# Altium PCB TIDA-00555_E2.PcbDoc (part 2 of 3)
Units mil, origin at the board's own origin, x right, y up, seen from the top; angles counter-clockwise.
Board outline 6490 x 3985 mil, 4 copper layers (Top Layer, MidLayer1, MidLayer2, Bottom Layer), stack 61.2 mil thick; 376 components, 194 nets, 936 pads, 294 vias.
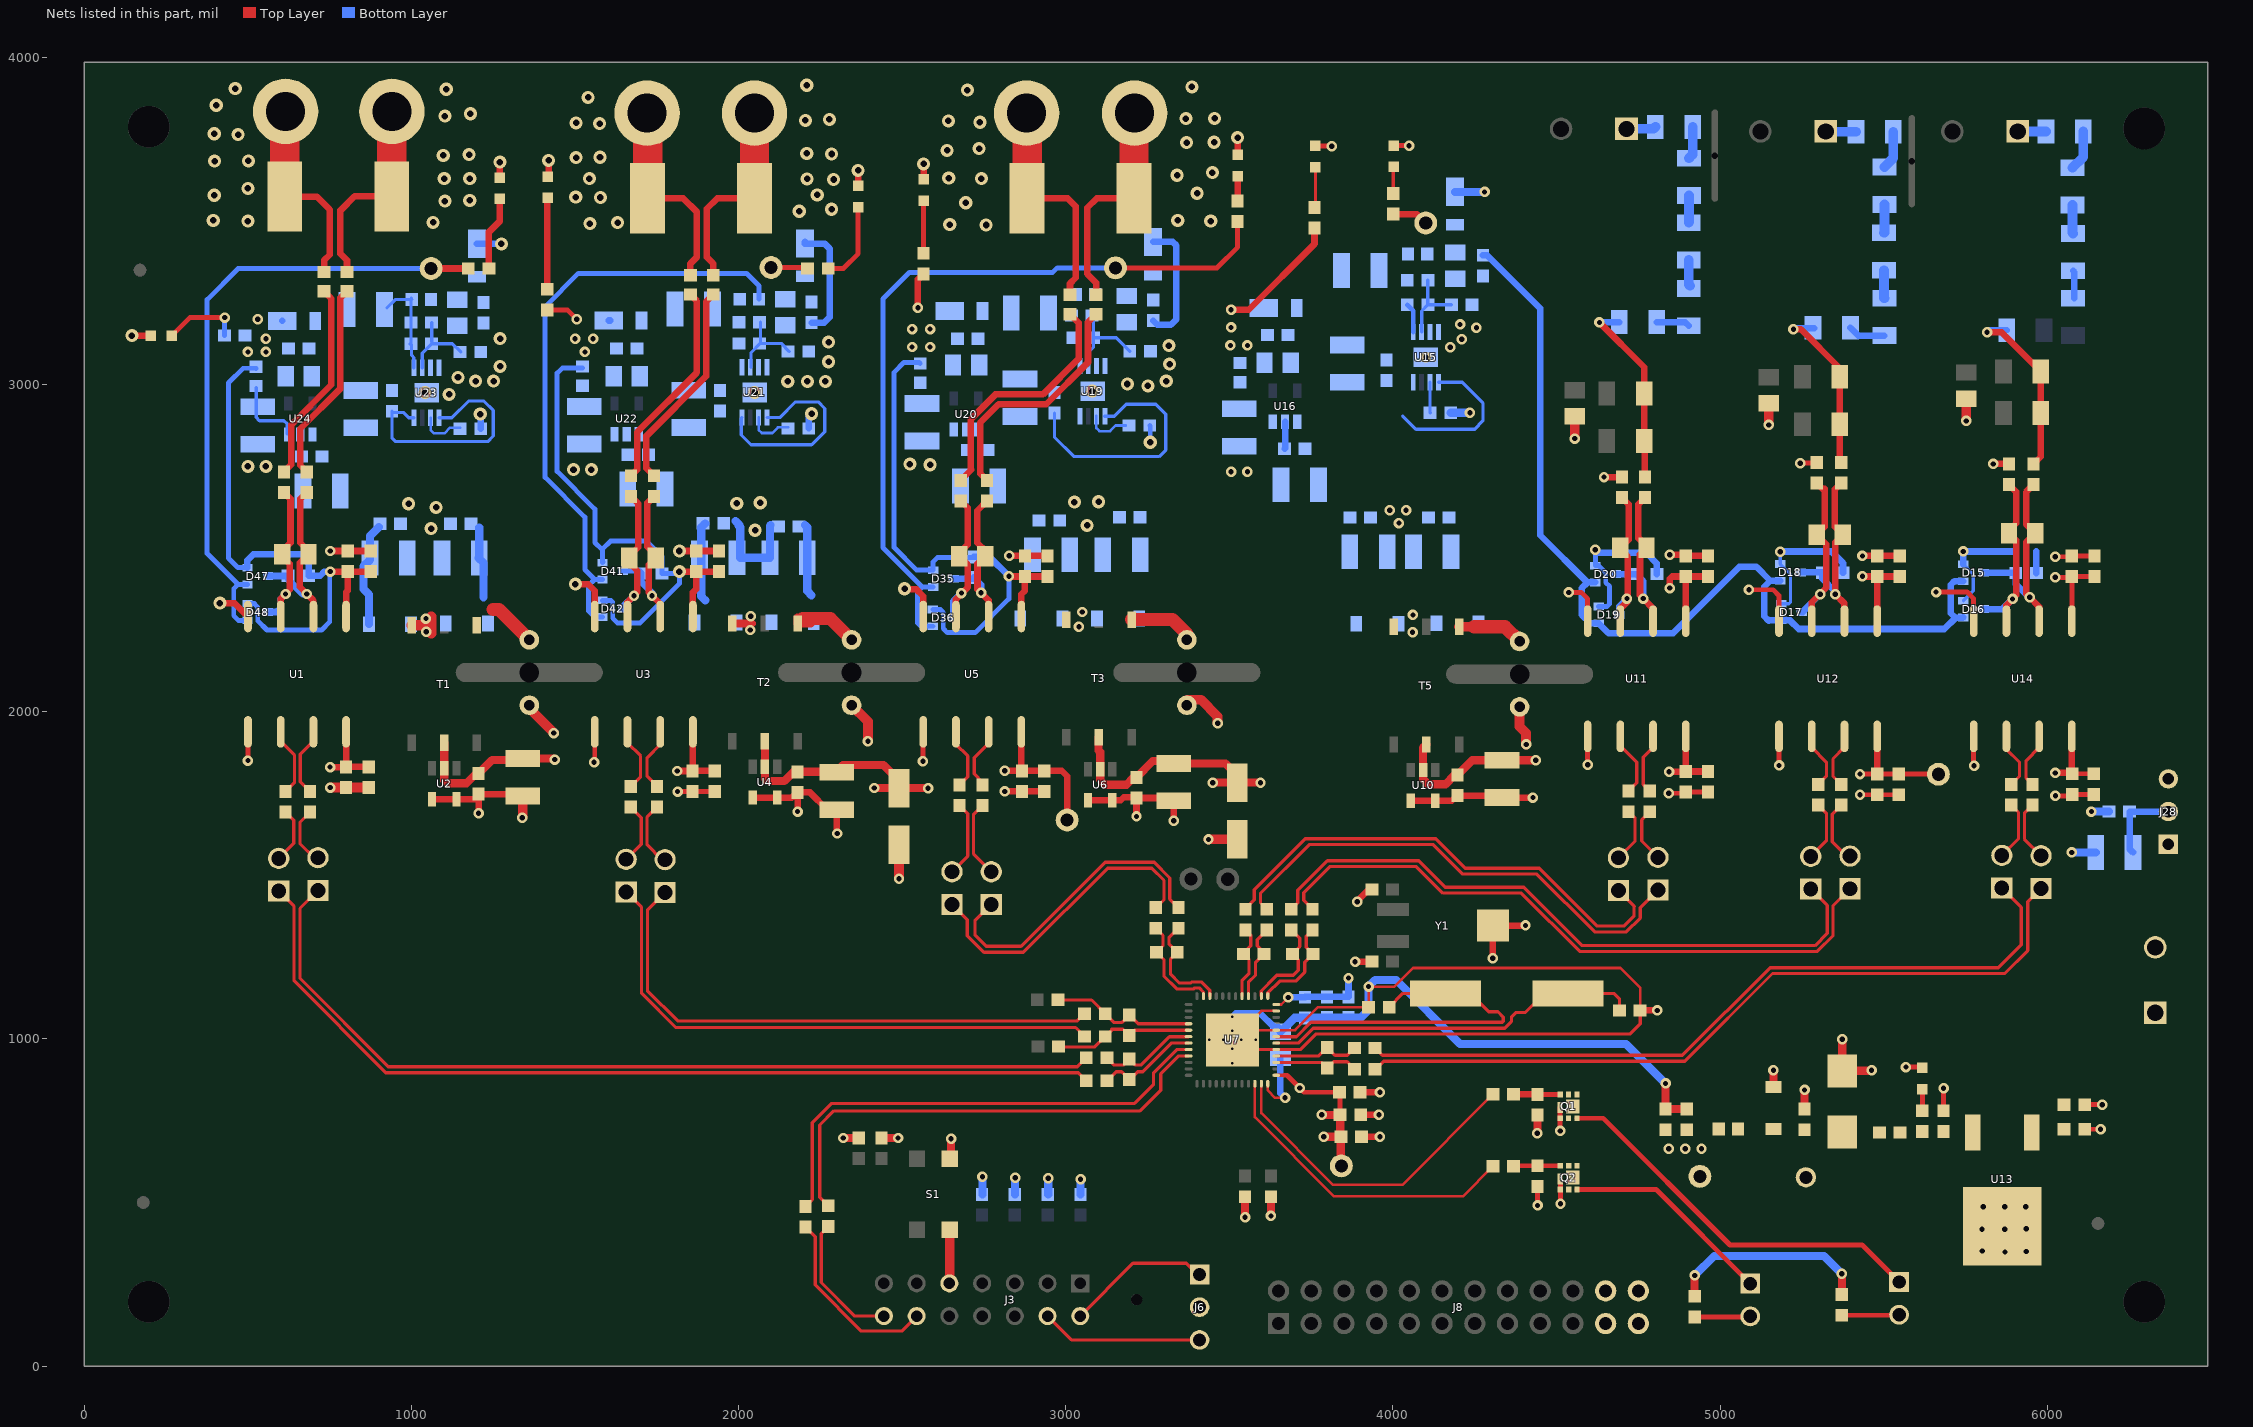
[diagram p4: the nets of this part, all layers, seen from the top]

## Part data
C1 C3 C4 C8 C11 C12 C17 C19 C20 C57 C64 C70: library part 06033C104JAT2A, "CAP, CERM, 0.1uF, 25V, +/-5%, X7R, 0603"
C2 C9 C18 C55 C61 C68: "CAP, CERM, 330 pF, 50 V, +/- 10%, C0G/NP0, 0805"
C5 C13 C23 C30 C49 C71 C75 C78 C80 C83 C85 C106 C109 C113 C114 C118 C120 C122 C125 C129 C130 C134 C136 C138 C141 C145 C146 C150 C152: library part C0603C104K5RACTU, "CAP, CERM, 0.1uF, 50V, +/-10%, X7R, 0603"
C6 C14 C25 C27 C50 C73 C77 C79 C81 C82 C86 C108 C112 C115 C116 C117 C121 C123 C128 C131 C132 C133 C137 C139 C144 C147 C148 C149 C153: library part GMK325AB7106MM-T, "CAP, CERM, 10uF, 35V, +/-20%, X7R, 1210"
C7 C15 C26 C51: library part 202R18W102KV4E, "CAP CER 1000PF 1KV 10% RADIAL"
C10: "CAP, CERM, 1000 pF, 50 V, +/- 10%, C0G/NP0, 0603"
C16 C28: "CAP, AL, 22uF, 25V, +/-20%, 0.76 ohm, SMD"
C21 C22 C24 C29 C32 C34: "CAP, CERM, 100 pF, 50 V, +/- 5%, C0G/NP0, 0603"
C31 C33 C35 C38 C42 C43 C44 C45 C54 C56 C60 C62 C63 C65 C67 C103: "CAP, CERM, 1 µF, 16 V, +/- 10%, X7R, 0603"
C36 C105: "CAP, CERM, 0.1 µF, 16 V, +/- 5%, X7R, 0603"
C37 C102: "CAP, CERM, 10uF, 25V, +/-20%, X5R, 0603"
C39 C48: "CAP, CERM, 18pF, 50V, +/-5%, C0G/NP0, 0603"
C40 C41: "CAP, CERM, 12pF, 50V, +/-5%, C0G/NP0, 0603"
C46 C47 C52: "CAP, CERM, 0.1uF, 25V, +/-5%, X7R, 0603"
C53: "CAP, CERM, 4.7uF, 10V, +/-10%, X5R, 0603"
C58 C66: "CAP, CERM, 0.1uF, 50V, +/-10%, X7R, 0603"
C59: "CAP, TA, 4.7uF, 35V, +/-10%, 1.9 ohm, SMD"
C72 C84 C110 C119 C126 C135 C142 C151: library part C2012X5R1H475K125AB, "CAP, CERM, 4.7uF, 50V, +/-10%, X5R, 0805"
C74 C76 C107 C111 C124 C127 C140 C143: library part 06031C103JAT2A, "CAP, CERM, 0.01uF, 100V, +/-5%, X7R, 0603"
D1 D2 D3 D4 D5 D6 D9 D11: library part "LED_LG L29K-G2J1-24-Z", "LED SmartLED Green 570NM"
D10 D12: "LED, 5MM, RED, TH"
D13: library part 1SMB5915BT3G, "DIODE ZENER 3.9V 500MW SOD123"
D14: "LED SmartLED Green 570NM"
D15 D16 D17 D18 D19 D20 D35 D36 D41 D42 D47 D48: library part BAV99WT1G, "Diode, P-N, 70V, 0.2A, SOT-323"
D21 D23 D32 D33 D37 D39 D43 D45: library part MBR0520LT1G, "Diode, Schottky, 20V, 0.5A, SOD-123"
D22 D24 D31 D34 D38 D40 D44 D46: library part DFLZ6V2-7, "Diode, Zener, 6.2V, 1W, PowerDI123"
FB1 FB2 FB3 FB4 FB5 FB6 FB7: "FERRITE CHIP 1000 OHM 300MA 0603"
FB9 FB11 FB12 R67 R68 R69 R70 R79 R80 R81 R82 R90 R91 R92 R93: "RES, 332 k, 1%, 0.25 W, 1206"
FB10 FB13 FB14 FB17 FB18 FB19 FB20 FB21 FB22: library part MMZ1608B102C, "FERRITE CHIP 1000 OHM 300MA 0603"
FID1 FID2 FID3 FID4 FID5 FID6: library part Fiducial, "Fiducial mark.  There is nothing to buy or mount."
J3: library part 0015912140, "Header, 7x2, 100mil, SMT"
J6 J28: library part 009155003301006, "3 pin berger"
J8: library part TSW-112-07-G-D, "Header, TH, 100mil, 12x2, Gold plated, 230 mil above insulator"
J10 J11 J18 J19 J20 J21 J22 J23 J24 J25 J26 J27: "Header, 2.54 mm, 2x1, Gold, TH"
J14 J15 J16 J17: "TERMINAL BLOCK 5.08MM VERT 2POS, TH"
LBL1: library part THT-14-423-10, "Thermal Transfer Printable Labels, 0.650\" W x 0.200\" H - 10,000 per roll"
Logo1: library part TI_Logo, "Texas Instrument Corporate Signature"
MH1 MH2 MH3 MH4: library part "NY PMS 440 0025 PH", "Mountin hole, NPTH Drill 3.2mm"
Q1 Q2: "MOSFET, N-CH, 30V, 22A, SON 2X2 MM"
R1 R9 R22: "RESISTOR, SMD, 0.003 OHM, 1%, 5W, 3921"
R2 R4 R11 R14 R24 R26 R63 R65 R74 R77 R86 R89: "RES, 12.0, 1%, 0.1 W, 0603"
R3 R5 R12 R15 R23 R25 R64 R66 R75 R78 R87 R88: library part CRCW060310R0FKEA, "RES, 10.0 ohm, 1%, 0.1W, 0603"
R6 R7 R19 R21 R33 R55 R57 R105: library part CRCW06033K90JNEA, "RES, 3.9k ohm, 5%, 0.1W, 0603"
R8 R10 R27 R28: "RES, 0 ohm, 5%, 0.1W, 0603"
R13: "RES, 47k ohm, 5%, 0.1W, 0603"
R16 R17 R18 R20: library part RNCF0603TKY10K0, "RES 10K OHM 1/10W 5% 0603 SMD"
R29 R30 R31 R32 R34 R35 R41 R42 R45 R48 R50 R51: "RES, 1.00 k, 0.1%, 0.1 W, 0603"
R39 R44 R47 R52 R97 R107: "RES, 160 k, 1%, 0.1 W, 0603"
R40 R43: "RES, 4.70k ohm, 1%, 0.1W, 0603"
R53 R54 R76: "RES, 300 ohm, 5%, 0.1W, 0603"
R56 R58: "RES, 330 ohm, 5%, 0.1W, 0603"
R59 R71 R83: "RES, 0 ohm, 5%, 0.125W, 0805"
R60 R72 R84: library part RC1206FR-072K4L, "RES SMD 1.02K OHM 1% 1/4W 1206"
R61 R73 R85: "RES, 2.40 k, 1%, 0.25 W, 1206"
R94 R99 R101 R103: library part CRCW060311K5FKEA, "RES, 11.5k ohm, 1%, 0.1W, 0603"
R95 R100 R102 R104: "RES, 3.16 k, 1%, 0.1 W, 0603"
R98: library part CRCW0805330KJNEA, "RES, 0 ohm, 5%, 0.125W, 0805"
S1: "Switch, Tactile, SPST-NO, 0.1A, 16V, SMT"
T1 T2 T3 T5: library part TRNSFMR, "Transformer 469uH SMD"
TP1 TP2 TP4 TP5 TP7 TP8: "Test Point,  Black, Thru Hole Color Keyed"
TP3 TP6 TP9 TP10 TP16 TP17: library part TP-040_RND, "Test Point, O.040 Hole"
TP11 TP12 TP13 TP15 TP18: "Test Point, O.040 Hole"
U1 U3 U5 U11 U12 U14: "Fully-Differential Isolation Amplifier, DUB0008A"
U2 U4 U6 U10: "Transformer Driver for Isolated Power Supplies, DBV0005A"
U7: library part MSP430FR5969IRGZ, "Mixed Signal Microcontroller, RGZ0048B"
U13: "IC, 300-mA 40-V LOW-DROPOUT REGULATOR WITH 25-uA QUIESCENT CURRENT"
U15 U19 U21: library part TPS7A3001DGNR, "-36V, -200mA, Ultralow-Noise, Negative Linear Regulator"
U16 U20 U22 U24: "Regulator, LDO, 5V, 0.15A, SOT23-5"
U23: "-36V, -200mA, Ultralow-Noise, Negative Linear Regulator"
Y1: "CRYSTAL, 32.768KHz, 6PF, +/- 20PPM, SMD-3P"
Y2: "Crystal, 8MHz, 18pF, SMD"
ZZ1: library part AssemblyNoteLabel, "This Assembly Note is for PCB labels only"
ZZ2: library part AssemblyNote, "These assemblies are ESD sensitive, ESD precautions shall be observed."
ZZ3: library part AssemblyNote, "These assemblies must be clean and free from flux and all contaminants. Use of no clean flux is not acceptable."
ZZ4: library part AssemblyNote, "These assemblies must comply with workmanship standards IPC-A-610 Class 2, unless otherwise specified."

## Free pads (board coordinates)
  oval 450x59.06 hole 60 slot 450 at 0 deg unplated mask+10: 0(1360,2120) 0(2345,2120) 0(3370,2120) 0(4387,2115)
  oval 20x282 hole 20 slot 282 at 90 deg unplated mask+5: 3(4984,3700) 3(5586,3683)

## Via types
v1: diameter 32, hole 16, Top Layer to Bottom Layer, tented both sides, 177 vias
v2: diameter 40, hole 20, Top Layer to Bottom Layer, tented both sides, 109 vias
v3: diameter 19.68, hole 7.87, Top Layer to Bottom Layer, tented both sides, 8 vias

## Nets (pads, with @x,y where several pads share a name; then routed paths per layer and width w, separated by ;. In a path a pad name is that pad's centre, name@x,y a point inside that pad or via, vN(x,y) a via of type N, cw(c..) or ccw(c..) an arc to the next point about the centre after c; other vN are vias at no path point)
+5.0V_PH: C11.1 C17.1 C19.1 C42.2 C43.2 C44.2 C84.2 C85.1 D15.2 D16.2 D17.2 D18.2 D19.2 D20.2 D24.1 FB14.2 R52.2 R55.2 R97.2 R107.2 U11.1 U12.1 U14.1 | length 2473
  Top Layer w15: v1(6024,2411) 6072.5,2411 C19.1@6075,2413.5 ; U14.1@6075,2277.18 C19.1@6075,2413.5 ; C44.2@6144,2413.5 C19.1@6075,2413.5
  Top Layer w20: v1@3500,3234 v1(3505,3229) 3559,3229 3760,3430 R55.2@3760,3478.52 ; v1(4846,2378) 4846,2406 4853.5,2413.5 C11.1@4895,2413.5 ; U11.1@4895,2277.18 C11.1@4895,2413.5 ; C42.2@4963,2413.5 C11.1@4895,2413.5 ; v1(5435,2414) 5435.5,2413.5 C17.1@5480,2413.5 ; U12.1@5480,2277.18 C17.1@5480,2413.5 ; C43.2@5549,2413.5 C17.1@5480,2413.5
  Bottom Layer w10: v1(5184,2489) 5183.5,2488.5 D18.2@5183.5,2451.59 5215,2420.09 5215,2335 5210,2330 5187.09,2330 D17.2@5186.5,2330.59 ; D16.2@5743.5,2339.59 5774,2370.09 5774,2420.09 D15.2@5743.5,2450.59
  Bottom Layer w15: v1(4618,2495) 4618.5,2494.5 D20.2@4618.5,2446.59 4628.66,2446.59 4650.25,2425 4650.25,2395 4662,2383.25 4662,2329.85 4653.74,2321.59 D19.2@4628.5,2321.59
  Bottom Layer w20: v1@4627,2486 4774,2486 4806.5,2453.5 R52.2@4806.5,2421 ; v1@5185,2490 5340,2490 5375.5,2454.5 R97.2@5375.5,2425 ; D15.2@5743.5,2450.59 5743,2451.09 v1(5743,2490) 5903.5,2490 ; R107.2@5966.5,2424 5966.5,2490
  other v1: 3503,3120 3555,3120 3505,3175
+5.0V_USH: C1.1 C31.2 C151.2 C152.1 D46.1 D47.2 D48.2 FB22.2 R39.2 R105.2 U1.1 | length 1805
  Top Layer w20: v1(751.5,2428.5) C1.1@805,2428.5 ; U1.1@800,2291.18 800,2365 805,2370 C1.1@805,2428.5 ; C1.1@810,2435 805,2430 C1.1@805,2428.5 ; C31.2@875,2428.5 C1.1@805,2428.5
  Bottom Layer w15: D47.2@494.09,2445 D47.2@498.5,2440.59 469.41,2440.59 440,2470 440,3005 485,3050 524.53,3050 FB22.2@525,3049.53 ; D48.2@498.5,2330.59 519.41,2330.59 530,2320 530,2278 558,2250 725,2250 750,2275 750,2427.01 v1(751.5,2428.5)
  Bottom Layer w20: D47.2@498.5,2440.59 498.5,2463.5 516,2481 669,2481 685.5,2464.5 R39.2@685.5,2416 721,2416 733.5,2428.5 v1(751.5,2428.5) ; D46.1@604.81,3195 D46.1@605,3195
  other v1: 500,3100 555,3100 555,3140 530,3200
+5.0V_VSH: C3.1 C33.2 C135.2 C136.1 D40.1 D41.2 D42.2 FB20.2 R7.2 R44.2 U3.1 | length 1791.9
  Top Layer w15: R7.2@1415,3228.5 1476.5,3228.5 v1(1505,3200)
  Top Layer w20: v2(1818.5,2428.5) C3.1@1870,2428.5 ; U3.1@1860,2291.18 1860,2365 1870,2375 C3.1@1870,2428.5 ; C33.2@1940,2428.5 C3.1@1870,2428.5
  Bottom Layer w15: FB20.2@1522.64,3050.53 1460.53,3050.53 1445,3035 1445,2735 1560.5,2619.5 1560.5,2517.5 1581,2497 1583.5,2497 ; D42.2@1583.5,2340.59 1609.41,2340.59 1615,2335 1615,2286 1629,2272 1699,2272 1818.5,2391.5 v2(1818.5,2428.5) 1813,2423 R44.2@1765.5,2423 1765.5,2474.5 1718,2522 1608.5,2522 1583.5,2497 ; D41.2@1585.22,2457.31 D41.2@1583.5,2455.59 1583.5,2497
  Bottom Layer w20: D40.1@1602.44,3196 D40.1@1607.44,3196
  other v1: 1530,3100 1500,3140 1555,3140
+5.0V_WSH: C8.1 C38.2 C119.2 C120.1 D34.1 D35.2 D36.2 FB18.2 R21.2 R47.2 U5.1 | length 1823.6
  Top Layer w20: v1(2548,3235) 2548,3321.5 R21.2@2565,3338.5 ; v1(2826,2414) 2826.5,2413.5 C8.1@2875,2413.5 ; U5.1@2863.98,2291.18 2863.98,2358.98 2875,2370 C8.1@2875,2413.5 ; C38.2@2944,2413.5 C8.1@2875,2413.5
  Bottom Layer w15: FB18.2@2555,3064.53 2552.03,3067.5 2505,3067.5 2475,3037.5 2475,2502 2543,2434 2593.09,2434 D35.2@2594.5,2432.59 2594.5,2458.5 2607,2471 2716.5,2471 R47.2@2719,2473.5 ; D36.2@2593.5,2312.59 2616.66,2312.59 2625.25,2304 2625.25,2254.75 2638,2242 2723,2242 2826,2345 v1(2826,2414)
  Bottom Layer w20: R47.2@2719,2473.5 2766.5,2473.5 v1(2826,2414)
  other v1: 2530,3115 2585,3115 2530,3170 2585,3170
+5V_CNTL: C5.2 C6.2 C13.2 C14.2 C16.1 C23.2 C25.2 C28.1 C49.2 C50.2 C65.1 C66.1 J17.1 J28.3 T1.2 T2.2 T3.2 T5.2 U2.2 U4.2 U6.2 U10.2 U13.1 | length 2507.9
  Top Layer w25: T1.2@1100,1905 U2.2@1100,1827.24 1100,1790 1108.44,1781.56 1167.85,1781.56 1196.29,1810 C5.2@1200,1810 ; C5.2@1205,1811.5 1246.5,1853 1335.91,1853 C6.2@1340,1857.09 1434.91,1857.09 v1(1438,1854) ; T2.2@2080,1910 U4.2@2080,1832.24 2080,1795 2086.91,1788.09 2139.52,1788.09 2167.92,1816.5 C13.2@2180,1816.5 C14.2@2298.5,1816.5 ; C14.2@2300,1815 C14.2@2298.5,1816.5 ; v1(2414,1767) 2414.39,1766.61 C16.1@2490,1766.61 ; v1(2579,1766) 2578.39,1766.61 C16.1@2490,1766.61 ; T3.2@3100,1922 3100,1882 3105,1877 U6.2@3105,1824.24 3105,1792 3120,1777 3185,1777 3206.5,1798.5 3215,1798.5 C23.2@3216,1799.5 3265.59,1849.09 3323,1849.09 C25.2@3330,1842.09 3488.09,1842.09 3524,1806.17 C28.1@3524,1783.61 ; v1(3449,1783) 3449.61,1783.61 C28.1@3524,1783.61 ; v1(3595,1783) 3594.39,1783.61 C28.1@3524,1783.61 ; T5.2@4102,1900.22 4092,1890.22 U10.2@4092,1822.47 4092,1795.22 4094.11,1793.12 4094.11,1791.49 4107.29,1778.31 4160.09,1778.31 4188.5,1806.72 C49.2@4197,1806.72 4242.37,1852.09 C50.2@4332.8,1852.09 v1(4436.27,1852.09) ; C14.2@2298.5,1816.5 2319.01,1837 2443,1837 2490,1790 C16.1@2490,1766.61
+6V_PH: C77.1 C80.1 C82.2 C83.1 D23.1 U16.2 | length 83.4
  Bottom Layer w20: C83.1@3668.5,2804 3670,2805.5 U16.2@3670,2886.76
+6V_USH: C144.1 C145.1 C149.2 C150.1 D45.1 U24.2 | length 322.9
  Bottom Layer w25: D45.1@869.53,2268 869.53,2358.85 853.5,2374.88 853.5,2445.12 872.91,2464.53 C144.1@872.91,2470 872.91,2537.91 C145.1@900,2565
+6V_VSH: C128.1 C129.1 C133.2 C134.1 D39.1 U22.2 | length 244.9
  Bottom Layer w25: 1897.64,2341 1885.73,2352.91 1885.73,2564.09 C129.1@1897.64,2576
+6V_WSH: C112.1 C113.1 C117.2 C118.1 D33.1 U20.2
-5.0V_PH: C71.1 C72.2 D15.1 D16.1 D17.1 D18.1 D19.1 D20.1 D22.2 FB13.2 R57.2 TP16.1 | length 3018
  Top Layer w20: R57.2@4001,3521.5 4072.5,3521.5 TP16.1@4100,3494
  Bottom Layer w20: C71.1@4275,3395.5 4287.5,3395.5 4450,3233 4450,2539.82 4594.41,2395.41 ; D20.1@4618.5,2395.41 4594.41,2395.41 ; D18.1@5183.5,2400.41 5153.41,2400.41 ; D16.1@5743.5,2288.41 5742.09,2287 5719,2287 ; D15.1@5743.5,2399.41 5716.41,2399.41 5705,2388 5705,2301 5719,2287 ; 4594.41,2395.41 4577,2378 4577,2296 4602.59,2270.41 D19.1@4628.5,2270.41 4658.91,2240 4856,2240 5059,2443 5110.82,2443 5153.41,2400.41 ; 5153.41,2400.41 5135,2382 5135,2292 5148,2279 5148.41,2279.41 D17.1@5186.5,2279.41 5213.59,2279.41 5240,2253 5685,2253 5719,2287
-5.0V_USH: C138.1 C142.2 D44.2 D47.1 D48.1 FB21.2 R6.2 TP3.1 | length 1932.8
  Top Layer w20: TP3.1@1065,3360 TP3.1@1060,3355 R6.2@1173.5,3355
  Bottom Layer w15: D48.1@498.5,2279.41 470.59,2279.41 456.5,2293.5 456.5,2376.5 469.41,2389.41 ; D47.1@498.5,2389.41 469.41,2389.41 ; TP3.1@1060,3355 470,3355 375,3260 375,2483.82 469.41,2389.41
-5.0V_VSH: C122.1 C126.2 D38.2 D41.1 D42.1 FB19.2 R19.2 TP6.1 | length 1951.5
  Top Layer w15: TP6.1@2107.5,3366.5 TP6.1@2099,3358 2207.64,3358 R19.2@2210.64,3355
  Bottom Layer w15: D42.1@1583.5,2289.41 1560,2289.41 1541.5,2307.91 1541.5,2386.5 1559.41,2404.41 ; D41.1@1583.5,2404.41 1559.41,2404.41 ; FB19.2@2062.17,3261 2062.17,3301.83 2024,3340 1510,3340 1408.5,3238.5 1408.5,2716.5 1530,2595 1530,2435 1559.41,2405.59 1559.41,2404.41
-5.0V_WSH: C106.1 C110.2 D31.2 D35.1 D36.1 FB17.2 R33.2 TP10.1 | length 2359.2
  Top Layer w15: TP10.1@3152,3357 3462,3357 3525,3420 R33.2@3525,3498.5
  Bottom Layer w15: D36.1@2593.5,2261.41 2556.59,2261.41 2546,2272 2546,2366 2561.41,2381.41 ; D35.1@2594.5,2381.41 2561.41,2381.41 ; TP10.1@3152,3357 2974,3357 2960,3343 2522,3343 2441,3262 2441,2501.82 2561.41,2381.41
-6V_PH: C73.2 C75.2 C78.1 C81.2 D21.2 U15.5 U15.8 | length 489.4
  Bottom Layer w10: 4030,2904 4070,2864 4250,2864 4275,2889 4275,2944 4211.6,3007.4 U15.5@4138.8,3007.4
-6V_USH: C139.2 C141.2 C146.1 C148.2 D43.2 U23.5 U23.8 | length 972.9
  Bottom Layer w10: C146.1@940,2918.5 C146.1@940,2915 ; U23.8@1007,2898.4 991.6,2898.4 975,2915 C146.1@940,2915 ; U23.5@1083.8,2898.4 1123.4,2898.4 1175,2950 1221.01,2950 1250,2921.01 1250,2843 1233,2826 952,2826 940,2838 C146.1@940,2915
  Bottom Layer w25: C139.2@1205,2470 1219.47,2455.53 1219.47,2350 ; C139.2@1207.09,2470 1207.09,2562.91
-6V_VSH: C123.2 C125.2 C130.1 C132.2 D37.2 U21.5 U21.8 | length 837.2
  Bottom Layer w10: U21.8@2009.64,2899.4 2007.64,2897.4 2007.64,2846 2037.64,2816 2222.64,2816 2263,2856.36 2263,2927 2243,2947 2173.64,2947 2126.04,2899.4 U21.5@2086.44,2899.4
  Bottom Layer w25: C125.2@2202.64,2571 2209.72,2563.91 C123.2@2209.72,2471 2209.72,2368.91 2222.64,2356
-6V_WSH: C108.2 C109.2 C114.1 C116.2 D32.2 U19.5 U19.8 | length 770.4
  Bottom Layer w10: C114.1@2965,2913.5 2965,2840 3025,2780 3285,2780 3305,2800 3305,2910 3275,2940 3185,2940 3148.4,2903.4 U19.5@3118.8,2903.4
A1_RX: R10.2 U7.21 | length 1501.6
  Top Layer w10: R10.2@2274,489.99 2248,515.99 2248,737 2291,780 3227,780 3290,843 3290,893 3344.94,947.94 U7.21@3375.14,947.94
A1_TX: R8.2 U7.20 | length 1528.2
  Top Layer w10: R8.2@2204,487.99 2225,508.99 2225,744 2284,803 3210,803 3268,861 3268,896.46 3339.16,967.62 U7.20@3375.14,967.62
AGND: C39.2 C48.2 C52.2 C53.2 C102.2 C103.2 C105.2 R98.1 U7.41 U7.44 U7.47 U7.49 | length 4705.2
  Top Layer w8: U7.49@3509,997.15 U7.49@3538.53,1026.68 ; U7.47@3642.86,1085.73 3597.58,1085.73 U7.49@3538.53,1026.68 ; C48.2@4755.5,1087 4755.5,1156.5 4695,1217 4061,1217 4004,1160 v1(3925.5,1160) C39.2@3925.5,1097 3771.05,1097 3700.72,1026.68 U7.44@3642.86,1026.68 U7.49@3538.53,1026.68
  Top Layer w10: U7.49@3509,997.15 3538.53,967.62 U7.41@3642.86,967.62 3716.62,967.62 3764,1015 4724,1015 4755.5,1046.5 C48.2@4755.5,1087
  Top Layer w20: C48.2@4755.5,1087 v1(4808,1087)
  Top Layer w25: v1(4833,864) C52.2@4833,785.5 C53.2@4898,785.5
  Bottom Layer w20: v3(3509,1068.01) 3519.49,1078.5 3593.5,1078.5 3635.87,1036.13 R98.1@3651.38,1036.13
  Bottom Layer w25: R98.1@3656,1022 3698.5,1064.5 C105.2@3731,1064.5 3732,1065.5 C103.2@3798,1065.5 C102.2@3864,1065.5 3902.5,1065.5 3925.5,1088.5 v1(3925.5,1160) 3945.5,1180 4010,1180 4205,985 4712,985 v1(4833,864)
  other v3: 3509,926.28 3509,969.59 3438.13,997.15 3481.44,997.15 3536.56,997.15 3579.87,997.15 3509,1024.71
AMC_VCC: C4.2 C12.2 C20.2 C27.1 C30.1 C45.1 C54.1 C56.1 C57.2 C60.1 C62.1 C64.2 C67.1 C70.2 J28.2 TP9.1 TP17.1 U1.8 U3.8 U5.8 U11.8 U12.8 U14.8 | length 1974.3
  Top Layer w15: v1(5427.5,1809.5) C64.2@5480,1809.5 C62.1@5546,1809.5 5666.5,1809.5 TP17.1@5667,1809 ; C70.2@6073.5,1813 6075,1811.5 C70.2@6076,1810.5 C67.1@6142,1810.5
  Top Layer w20: v1(751,1831) 799.5,1831 C4.2@800,1831.5 ; U1.8@800,1938.82 C4.2@800,1831.5 ; C45.1@869,1831.5 C4.2@800,1831.5 ; v1(1812,1819) 1858.5,1819 C12.2@1859,1819.5 ; U3.8@1860,1938.82 1860,1820.5 C12.2@1859,1819.5 ; C54.1@1927,1819.5 C12.2@1859,1819.5 ; v1(2813,1819.5) C20.2@2866,1819.5 ; U5.8@2863.98,1938.82 2863.98,1821.52 C20.2@2866,1819.5 ; TP9.1@3004,1669 3004,1803 2987.5,1819.5 C56.1@2934,1819.5 C20.2@2866,1819.5 ; v1(4844,1817) 4894.5,1817 C57.2@4895,1817.5 ; U11.8@4895,1924.82 C57.2@4895,1817.5 ; C60.1@4963,1817.5 C57.2@4895,1817.5 ; C64.2@5480,1809.5 U12.8@5480,1924.82 ; v1(6024,1813) C70.2@6073.5,1813 ; C70.2@6075,1811.5 U14.8@6075,1924.82
  Bottom Layer w20: C27.1@6262.09,1570 6251.5,1580.59 C30.1@6251.5,1695 J28.2@6370,1695
AVCC: C52.1 C53.1 C102.1 C103.1 C105.1 FB7.2 J28.1 TP15.1 U7.48 | length 287.5
  Top Layer w8: U7.48@3642.86,1105.42 3658.42,1105.42 v1(3680,1127)
  Bottom Layer w20: v1@3680.5,1127.5 C105.1@3731,1127.5 3732,1128.5 C103.1@3798,1128.5 C102.1@3864,1128.5 v1(3864,1186)
  other v1: 4843,664 4893,664 4943,664
DGND: C4.1 C5.1 C6.1 C7.1 C10.2 C12.1 C13.1 C14.1 C15.1 C16.2 C20.1 C23.1 C25.1 C26.1 C27.2 C28.2 C30.2 C35.2 C36.2 C37.2 C40.2 C41.2 C45.2 C46.2 C47.2 C49.1 C50.1 C51.1 C54.2 C56.2 C57.1 C58.2 C59.2 C60.2 C62.2 C63.2 C64.1 C65.2 C66.2 C67.2 C70.1 D13.2 D14.1 J3.9 J8.22 J8.24 J17.2 Q1.4 Q1.7 Q2.4 Q2.7 R98.2 S1.3 S1.4 U1.5 U2.4 U2.5 U3.5 U4.4 U4.5 U5.5 U6.4 U6.5 U7.36 U10.4 U10.5 U11.5 U12.5 U13.2 U14.5 Y1.3 | length 5492.2
  Top Layer w8: U7.36@3617.27,863.29 3617.27,842.73 3640,820 v1(3670,820)
  Top Layer w15: v1(500,1851) U1.5@500,1938.82 ; v1(1558,1846) 1560,1848 U3.5@1560,1938.82 ; v1(1813,1756) 1858.5,1756 C12.1@1859,1756.5 C54.2@1927,1756.5 ; v1(2563,1849) 2563.98,1849.98 U5.5@2563.98,1938.82 ; v1(4442,491) C47.2@4442,549.5 ; v1(4511,719) Q1.4@4511,757.46 Q1.7@4511,790 ; Q2.7@4511.41,572.22 Q2.4@4511.41,539.68 4512,539.09 v1(4512,496) ; v1(4595,1838) U11.5@4595,1924.82 ; v1(4843,1751) 4891.5,1751 C57.1@4895,1754.5 C60.2@4963,1754.5 ; v1(5180,1836) U12.5@5180,1924.82 ; v1(5427.5,1746.5) C64.1@5480,1746.5 C62.2@5546,1746.5 ; v1(5568,914) 5615.48,914 D14.1@5618,911.48 ; C63.2@5683,780.5 v1(5683,849) ; U14.5@5775,1924.82 5775,1836 v1(5776,1835) ; v1(6025,1743) 6071.5,1743 C70.1@6076,1747.5 C67.2@6142,1747.5 ; C66.2@6114.5,724 v1(6163,724) ; C65.2@6114.5,799 v1(6168,799)
  Top Layer w20: U2.4@1062.6,1732.76 U2.5@1137.4,1732.76 1192.76,1732.76 C5.1@1205,1745 ; v1(1205,1690) C5.1@1205,1745 ; C6.1@1320,1750 1318.5,1748.5 C5.1@1205,1748.5 C5.1@1205,1745 ; U4.4@2042.6,1737.76 2112.24,1737.76 U4.5@2115,1735 ; U4.5@2117.4,1737.76 2162.76,1737.76 C13.1@2180,1755 ; v1(2180,1695) C13.1@2180,1753.5 2218,1753.5 2270.68,1700.83 C14.1@2300,1700.83 2300,1629 v1(2301,1628) ; v1(2813,1756.5) C20.1@2866,1756.5 C56.2@2934,1756.5 ; U6.4@3068,1729.35 U6.4@3067.6,1729.76 U6.5@3142.4,1729.76 3167.76,1729.76 3177,1739 3213.5,1739 C23.1@3216,1736.5 ; v1(3216,1680) C23.1@3216,1736.5 ; v1(3330,1667) C25.1@3330,1727.91 3321.41,1736.5 C23.1@3216,1736.5 ; v1(3884,1236) 3884.55,1236.55 C41.2@3935.61,1236.55 ; v1(3891,1419) 3888,1419 3925.55,1456.55 C40.2@3935.61,1456.55 ; C36.2@3899.5,837 v1(3960,837) ; C35.2@3901.5,768 v1(3957,768) ; C37.2@3903.5,701 v1(3960,701) ; U10.4@4054.6,1727.98 4124.76,1727.98 U10.5@4127,1730.22 ; U10.5@4129.4,1727.98 4179.76,1727.98 C49.1@4197,1745.22 ; C49.1@4197,1743.73 4315.5,1743.73 C50.1@4317,1745.22 ; Y1.3@4300,1351.93 Y1.3@4305.38,1346.55 ; v1(4305,1247) 4305.38,1247.38 Y1.3@4305.38,1346.55 ; C50.1@4332.8,1737.91 v1(4427.89,1737.91) ; v1(4405,1347) 4404.55,1346.55 Y1.3@4305.38,1346.55 ; v1(5804,487) 5860.11,430.89 U13.2@5863,430.89
  Top Layer w25: C10.2@2436.76,697.23 v1(2487.27,697.23) ; S1.4@2649,633.27 v1@2649,695 ; v1(4441,712) 4441.59,712.59 C46.2@4441.59,767.28 ; D13.2@5163,853.47 v1(5163,904) ; C58.2@5258,785.5 v1(5258,844) ; v1(5373,999) C59.2@5373,902.5 5461.5,902.5 v1(5463,904)
  Top Layer w30: v1(751.5,1768.5) C4.1@800,1768.5 C45.2@869,1768.5 ; v1(1338.54,1676.46) 1340,1677.91 C6.1@1340,1742.91 ; C7.1@1360,2020 1360,2010 v1(1435,1935) ; C15.1@2335,2030 C15.1@2345,2020 2395,1970 v1(2395,1910) ; v1(2490,1490) C16.2@2490,1593.39 ; J3.9@2644,253 2645,254 S1.3@2645,416.73 ; C26.1@3369.29,2037.01 3412.99,2037.01 3463.98,1986.02 v1(3463.98,1965) ; v1(3436,1610) 3436.39,1610.39 C28.2@3524,1610.39 ; C51.1@4387,2015.22 C51.1@4387,2015 4387,1955.22 4407,1935.22 v1(4407,1900.22)
  Bottom Layer w20: R98.2@3656,942 3656,834 v1(3670,820)
  Bottom Layer w25: v1(6075,1570) C27.2@6147.91,1570 ; v1(6135,1695) C30.2@6188.5,1695
  other v1: 5871,349 5936,350 5801,352 5800,418 5870,418 5936,420 5870,487 5934,487 2649.27,695.27
DOUTN_CH_U: J11.1 R32.1 | length 2841.9
  Top Layer w10: J11.1@594,1452 641,1405 641,1177.54 921.54,897 3037.65,897 R32.1@3062.5,872.15
DOUTN_CH_U1: J11.2 R3.2 | length 170.9
  Top Layer w10: J11.2@594,1552 640,1598 640,1668.5 R3.2@615,1693.5
DOUTN_CH_V: J19.1 R30.1 | length 1738
  Top Layer w10: J19.1@1656,1449 1703,1402 1703,1140 1808,1035 3029.65,1035 R30.1@3057.5,1007.15
DOUTN_CH_V1: J19.2 R12.2 | length 191.8
  Top Layer w10: J19.2@1656,1549 1702,1595 1702,1676.5 R12.2@1670,1708.5
DOUTN_CH_W: J21.1 R34.1 | length 953.1
  Top Layer w10: J21.1@2652,1411 2699,1364 2699,1315.54 2749.54,1265 2870.46,1265 3127.46,1522 3262.54,1522 3300,1484.54 3300,1425 3276.5,1401.5 R34.1@3275,1401.5
DOUTN_CH_W1: J21.2 R23.2 | length 232.7
  Top Layer w10: J21.2@2652,1511 2700,1559 2700,1688.5 R23.2@2675,1713.5
DOUTN_U_PH: J23.1 R41.1 | length 1534.5
  Top Layer w10: R41.1@3549,1396.48 3549,1397.7 3576.27,1424.96 3576.27,1456.27 3732,1612 4131,1612 4221,1522 4447.46,1522 4624.46,1345 4706,1345 4737,1376 ; J23.1@4689,1454 4738,1405 4737,1404 4737,1376 ; 4737,1392 4737,1376
DOUTN_U_PH1: J23.2 R64.2 | length 169.9
  Top Layer w10: J23.2@4689,1554 4740,1605 4740,1674.5 R64.2@4720,1694.5
DOUTN_V_PH: J25.1 R45.1 | length 2000.8
  Top Layer w10: R45.1@3689,1396.48 3708.8,1416.28 3708.8,1454.26 3799.54,1545 4079,1545 4160,1464 4399.46,1464 4577.96,1285.5 5290.04,1285.5 5327,1322.46 5327,1408 J25.1@5277,1458
DOUTN_V_PH1: J25.2 R75.2 | length 186.7
  Top Layer w10: J25.2@5277,1558 5325,1606 5325,1689.5 R75.2@5300,1714.5
DOUTN_W_PH: J27.1 R50.1 | length 2321.1
  Top Layer w10: R50.1@3945.5,972.15 3967.64,950 4884.54,950 5152.54,1218 5850,1218 5920,1288 5920,1402 J27.1@5861,1461
DOUTN_W_PH1: J27.2 R87.2 | length 183.7
  Top Layer w10: J27.2@5861,1561 5912,1612 5912,1692.5 R87.2@5890,1714.5
DOUTP_CH_U: J10.1 R31.1 | length 2818.4
  Top Layer w10: J10.1@714,1454 659,1399 659,1185 929,915 3035.36,915 R31.1@3062.5,942.15
DOUTP_CH_U1: J10.2 R5.2 | length 195.2
  Top Layer w10: R5.2@690,1693.5 659,1662.5 659,1597 702,1554 J10.2@714,1554 ; J10.2@711,1554 J10.2@714,1554 ; J10.2@724,1554 J10.2@714,1554
DOUTP_CH_V: J18.1 R29.1 | length 1706.9
  Top Layer w10: J18.1@1775,1448 1721,1394 1721,1147.46 1813.46,1055 3035.36,1055 R29.1@3057.5,1077.15
DOUTP_CH_V1: J18.2 R15.2 | length 201.5
  Top Layer w10: R15.2@1750,1708.5 1720,1678.5 1720,1593.16 1765.16,1548 J18.2@1775,1548
DOUTP_CH_W: J20.1 R35.1 | length 951.9
  Top Layer w10: J20.1@2772,1411 2722,1361 2722,1318 2757,1283 2863,1283 3120,1540 3270,1540 3318,1492 3318,1427.46 R35.1@3344,1401.46
DOUTP_CH_W1: J20.2 R25.2 | length 236.1
  Top Layer w10: R25.2@2745,1713.5 2718,1686.5 2718,1565 J20.2@2772,1511
DOUTP_U_PH: J22.1 R42.1 | length 1515.2
  Top Layer w10: R42.1@3614,1396.48 3595,1415.48 3595,1445 3744,1594 4123.54,1594 4213.54,1504 4440,1504 4617,1327 4671,1327 4713.46,1327 4756,1369.54 4756,1390 4756,1401 J22.1@4810,1455
DOUTP_U_PH1: J22.2 R66.2 | length 170.6
  Top Layer w10: R66.2@4785,1694.5 4760,1669.5 4760,1605 J22.2@4810,1555
DOUTP_V_PH: J24.1 R48.1 | length 2005.7
  Top Layer w10: R48.1@3754,1396.48 3726.8,1423.68 3726.8,1446.8 3807,1527 4071.54,1527 4152.54,1446 4392,1446 4570.5,1267.5 5297.5,1267.5 5345,1315 5345,1407 J24.1@5397,1459
DOUTP_V_PH1: J24.2 R78.2 | length 194.8
  Top Layer w10: R78.2@5370,1714.5 5343,1687.5 5343,1603.16 5387.16,1559 J24.2@5397,1559
DOUTP_W_PH: J26.1 R51.1 | length 2351.8
  Top Layer w10: R51.1@3945.5,907.15 3946.78,907.15 3971.63,932 4892,932 5160,1200 5870,1200 5940,1270 5940,1419 J26.1@5981,1460
DOUTP_W_PH1: J26.2 R88.2 | length 186
  Top Layer w10: R88.2@5955,1714.5 5930,1689.5 5930,1611 J26.2@5981,1560
DVCC: C35.1 C36.1 C37.1 C58.1 C59.1 D13.1 FB7.1 FB10.2 J6.2 J8.21 J8.23 R13.2 R16.1 R17.1 R18.1 R20.1 R40.1 R43.1 R56.2 R58.2 TP13.1 TP18.1 U7.37 | length 1544.1
  Top Layer w10: U7.37@3642.86,888.88 3666,888.88
  Top Layer w15: 3666,888.88 3676.12,888.88 v1(3715,850) 3728,837 C36.1@3836.5,837 3838.5,835 C35.1@3838.5,768
  Top Layer w25: v1(2319.76,697.23) R13.2@2366.76,697.23 ; v1(3548,455) R40.1@3548,517.5 ; v1(3627,459) R43.1@3627,517.5 ; v1(3782,768) C35.1@3838.5,768 3838.5,703 C37.1@3840.5,701 ; v1(3788,701) C37.1@3840.5,701 ; TP13.1@3842,612 3840.5,613.5 C37.1@3840.5,701 ; R56.2@4922,213.5 v1(4922,277) ; R58.2@5372,218.5 v1(5372,282)
  Bottom Layer w25: R16.1@2745,524.99 v1(2745,578.5) ; R17.1@2845,524.99 v1(2845,575.5) ; R18.1@2946,524.99 v1(2946,574.5) ; R20.1@3045,524.5 v1(3045,571) ; v1(4922,277) 4982,337 5317,337 v1(5372,282)
EXT: J3.4 J6.3 | length 498.1
  Top Layer w10: J3.4@2944,153 3017,80 3402,80 J6.3@3409,73
GND_PH: C11.2 C17.2 C19.2 C42.1 C43.1 C44.1 C51.2 C71.2 C72.1 C73.1 C74.1 C75.1 C77.2 C78.2 C79.1 C80.2 C81.1 C82.1 C83.2 C84.1 C85.2 C86.1 D9.1 D11.2 D22.1 D24.2 R59.2 R63.1 R71.2 R74.1 R83.2 R86.1 R94.1 T5.4 U11.4 U12.4 U14.4 U15.3 U15.4 U15.9 U16.1 | length 1666
  Top Layer w15: D9.1@3763,3729.5 3812.52,3729.5 v1(3813,3729.02) ; D11.2@4003,3730.48 4048.52,3730.48 v1(4049,3730) ; v1(4537,2365) 4575,2365 4595,2345 U11.4@4595,2277.18 ; v1(5088,2373) 5162,2373 5180,2355 U12.4@5180,2277.18 ; v1(5245,2760) 5292.5,2760 R74.1@5295,2762.5 ; v1(5660,2366) 5755,2366 5775,2346 U14.4@5775,2277.18 ; v1(6024,2473.99) 6072.5,2473.99 C19.2@6075,2476.5 C44.1@6144,2476.5
  Top Layer w20: v1(4645,2717.5) R63.1@4700,2717.5 R63.1@4700,2718.72 ; v1(4846,2480) 4891.5,2480 C11.2@4895,2476.5 C42.1@4963,2476.5 ; v1@5431.5,2476.5 v1(5435,2476.5) C17.2@5480,2476.5 C43.1@5549,2476.5 ; v1(5835,2757.48) R86.1@5882.73,2757.48
  Top Layer w30: T5.4@4202,2260.07 4247,2260.07 ; v1(4555.72,2835) R59.2@4555.72,2903 ; v1(5148.72,2877) R71.2@5148.72,2943 ; v1(5752,2889) R83.2@5752,2957
  Top Layer w40: 4247,2260.07 4342.16,2260.07 C51.2@4387,2215.22
  Bottom Layer w25: C74.1@4176.5,2914 v1(4235,2914) ; D22.1@4190,3589.2 4279.8,3589.2 v1(4280,3589)
  other v1: 4018,2577 3990,2616 4040,2616 3505,2734 3555,2734 4100.8,3084 4175,3114 4210,3139 4255,3174 4205,3184
GND_USH: C1.2 C7.2 C31.1 C138.2 C139.1 C140.1 C141.1 C142.1 C144.2 C145.2 C146.2 C147.1 C148.1 C149.1 C150.2 C151.1 C152.2 C153.1 D1.1 D2.2 D44.1 D46.2 FB1.1 R1.1 R103.1 T1.4 TP1.1 U1.4 U23.3 U23.4 U23.9 U24.1 | length 1152.8
  Top Layer w20: v2(145,3150) D1.1@202.52,3150 ; v2(414,2332) 459.18,2332 U1.4@500,2291.18 ; R1.1@612.61,3576 R1.1@612.61,3575 710,3575 750,3535 750,3397.31 732.68,3380 FB1.1@732.68,3344.53 ; v1(751.5,2491.5) C1.2@805,2491.5 C31.1@875,2491.5 ; D2.2@1270,3632.48 v2(1270,3680)
  Top Layer w40: 1249,2312.5 1267.5,2312.5 C7.2@1360,2220
  Top Layer w90: R1.1@612.61,3576 TP1.1@612.61,3775
  Bottom Layer w20: D44.1@1200,3430.2 v2(1274.8,3430.2) ; v2(1210,2910) 1211.5,2908.5 C140.1@1211.5,2865
  other v2: 1060,2560 1075,2625 991,2636 500,2750 555,2750 1115,2970 1040.81,2975.81 1195.81,3010.81 1250.81,3010.81 1142,3022 1270.81,3055.81 1270.81,3140.81 500,3500 394,3502 397,3579 500,3600 398,3683 501,3684 470,3764 397,3767 403,3854 461,3905
GND_VSH: C3.2 C15.2 C33.1 C122.2 C123.1 C124.1 C125.1 C126.1 C128.2 C129.2 C130.2 C131.1 C132.1 C133.1 C134.2 C135.1 C136.2 C137.1 D3.1 D4.2 D38.1 D40.2 FB3.1 R9.1 R101.1 T2.4 TP4.1 U3.4 U21.3 U21.4 U21.9 U22.1 | length 1872.7
  Top Layer w20: D3.1@1415.75,3636.06 1418.75,3639.06 v2(1418.75,3685.58) ; v2(1500.71,2390) 1540,2390 1560,2370 U3.4@1560,2291.18 ; R9.1@1721.61,3570 1830,3570 1872.32,3527.69 1872.32,3390 1852.32,3370 FB3.1@1852.32,3334.53 ; v2(1818.5,2491.5) C3.2@1870,2491.5 C33.1@1940,2491.5 ; D4.2@2365,3607.48 v2(2365,3655)
  Top Layer w25: T2.4@2180,2288.5 T2.4@2180,2269.84 2220.16,2269.84
  Top Layer w40: 2195,2285 2280,2285 C15.2@2335,2230
  Top Layer w90: TP4.1@1720,3770 1721.61,3768.39 R9.1@1721.61,3570
  Bottom Layer w20: D38.1@2202.64,3436 D38.1@2202.64,3431.2 2262.44,3431.2 2277.64,3416 2277.64,3206 2261.14,3189.5 C122.2@2222.64,3189.5 ; C124.1@2214.13,2866 2214.13,2902.5 v2(2222.64,2911)
  Bottom Layer w25: 1990.55,2583.09 2002.64,2571 ; 2000.14,2568.5 2004.72,2563.91 2004.72,2471 C123.1@2095.55,2471 2095.55,2568.91 2097.64,2571
  other v2: 2050,2555 1994,2637 2066,2639 1495,2740 1550,2740 2048.44,2976 2150,3010 2210,3010 2265,3010 2275,3070 2275,3130 1545,3492 1630,3495 1577,3572 1502,3573 1543.8,3629.87 1503,3694 1576,3695 1575,3798 1503,3800 1540,3878
GND_WSH: C8.2 C26.2 C38.1 C106.2 C107.1 C108.1 C109.1 C110.1 C112.2 C113.2 C114.2 C115.1 C116.1 C117.1 C118.2 C119.1 C120.2 C121.1 D5.1 D6.2 D31.1 D34.2 FB5.1 R22.1 R99.1 T3.4 TP7.1 U5.4 U19.3 U19.4 U19.9 U20.1 | length 1604.2
  Top Layer w20: v2@2508,2375 2542,2375 2563.98,2353.02 U5.4@2563.98,2291.18 ; D5.1@2565,3627.48 v2(2565,3675) ; v1(2827,2477) 2875,2477 2875.5,2476.5 C38.1@2944,2476.5 ; R22.1@2881.61,3570 3005,3570 3030.37,3544.63 3030.37,3326.66 3012.69,3308.98 FB5.1@3012.69,3274.53 ; D6.2@3525,3702.48 v2(3525,3755)
  Top Layer w40: T3.4@3201,2281.84 3326.16,2281.84 C26.2@3370,2238
  Top Layer w90: TP7.1@2880,3770 2881.61,3768.39 R22.1@2881.61,3570
  Bottom Layer w15: C107.1@3256.5,2875 3258,2873.5 v2(3258,2824)
  Bottom Layer w20: C106.2@3267,3195.5 3279.5,3183 3321,3183 3338,3200 3338,3425 3326.8,3436.2 D31.1@3267,3436.2
  other v2: 2507,2376 3065,2570 3026,2641 3100,2642 2585,2755 2523,2757 3080.8,2980 3251,2996 3188,3002 3307,3011 3317,3063 3315,3119 2756,3488 2645,3489 2694,3556 2742,3630 2642,3631 2637,3716 2735.13,3721.2 2737,3802 2641,3806 2699,3900
INT: J3.2 J6.1 | length 443.7
  Top Layer w10: J3.2@3044,153 3205,314 3368,314 J6.1@3405.5,276.5
LED1: R53.1 U7.35 | length 1003.4
  Top Layer w8: U7.35@3597.58,863.29 3597.58,773.42 3817,554 4028.5,554 R53.1@4305.5,831
LED2: R54.1 U7.34 | length 968.2
  Top Layer w8: U7.34@3577.9,863.29 3577.9,761.1 3820,519 4213.5,519 R54.1@4305.5,611
NetC2_1: C2.1 D47.3 R4.2 R39.1 U1.2 | length 590.4
  Top Layer w20: R4.2@680,2670.5 660,2650.5 660,2517 685,2492 C2.1@685,2482 ; C2.1@685,2467 C2.1@685,2482 ; U1.2@700,2291.18 700,2340 v1(680,2360) 658,2382 658,2455 C2.1@685,2482
  Bottom Layer w20: D47.3@561.5,2415 621.5,2415 R39.1@622.5,2416 622.5,2404.5 667,2360 v1(680,2360)
NetC2_2: C2.2 D48.3 R2.2 U1.3 | length 514.8
  Top Layer w20: U1.3@600,2291.18 600,2345 v1(615,2360) 628,2373 628,2452 C2.2@607,2473 ; C2.2@605,2467 C2.2@605,2482 605,2492 630,2517 630,2558.5 ; R2.2@610,2670.5 630,2650.5 630,2560
  Bottom Layer w20: D48.3@561.5,2305 586.91,2305 600,2318.09 600,2345 v1(615,2360)
NetC9_1: C9.1 D41.3 R14.2 R44.1 U3.2 | length 549.5
  Top Layer w20: R14.2@1741,2658.5 1721,2638.5 1721,2505 1746,2480 C9.1@1746,2470 1725,2449 1725,2365 v1(1735,2355) 1760,2330 U3.2@1760,2291.18
  Bottom Layer w15: D41.3@1646.5,2430 R44.1@1695.5,2430
  Bottom Layer w20: R44.1@1695.5,2430 R44.1@1702.5,2423 1702.5,2396.5 1735,2364 v1(1735,2355)
NetC9_2: C9.2 D42.3 R11.2 U3.3 | length 463.9
  Top Layer w20: U3.3@1660,2291.18 1660,2335 v1(1680,2355) 1690,2365 1690,2431 1666,2455 C9.2@1666,2470 1666,2476 1693,2503 1693,2636.5 R11.2@1671,2658.5
  Bottom Layer w20: D42.3@1646.5,2315 1646.5,2321.5 v1(1680,2355)
NetC18_1: C18.1 D35.3 R26.2 R47.1 U5.2 | length 518.7
  Top Layer w20: R26.2@2759,2644.5 2729.02,2614.52 2729.02,2517.01 2754,2492.02 C18.1@2754,2476 2730,2452 2730,2375 v1(2741,2364) 2763.98,2341.02 U5.2@2763.98,2291.18
  Bottom Layer w20: D35.3@2657.5,2407 2715.5,2407 R47.1@2719,2410.5 2741,2388.5 v1(2741,2364)
NetC18_2: C18.2 D36.3 R24.2 U5.3 | length 484.6
  Top Layer w20: U5.3@2663.98,2291.18 2663.98,2343.98 2700,2380 2700,2450 C18.2@2674,2476 2674,2484.98 2700.02,2511 2700.02,2623.48 R24.2@2679,2644.5
  Bottom Layer w20: D36.3@2656.5,2287 2656.5,2338.5 v1(2680.99,2362.99)
NetC21_1: C21.1 R28.2 R30.2 U7.17 | length 437.5
  Top Layer w10: R28.2@2977.5,977 2979.05,975.45 3088.8,975.45 R30.2@3120.5,1007.15 3140,1026.65 3140,1030 3174.65,1030 C21.1@3194,1010.65 3210.02,1026.68 U7.17@3375.14,1026.68
NetC21_2: C21.2 R27.2 R29.2 U7.16 | length 449.8
  Top Layer w10: R27.2@2975.5,1120 2976.5,1119 3078.64,1119 R29.2@3120.5,1077.15 3147.7,1049.95 3170.3,1049.95 C21.2@3194,1073.64 3221.28,1046.36 U7.16@3375.14,1046.36
NetC22_1: C22.1 R32.2 U7.19 | length 317
  Top Layer w10: R32.2@3125.5,872.15 3126.72,872.15 3153.98,899.41 3170.24,899.41 C22.1@3194,875.65 3195.65,875.65 3220,900 3235,900 3322.31,987.31 U7.19@3375.14,987.31
NetC22_2: C22.2 R31.2 U7.18 | length 310.3
  Top Layer w10: R31.2@3125.5,942.15 3147.64,920 3175.36,920 C22.2@3194,938.64 3212.64,920 3229.54,920 3316.53,1006.99 U7.18@3375.14,1006.99
NetC24_1: C24.1 R34.2 U7.11 | length 328.3
  Top Layer w10: R34.2@3275,1338.5 3297,1316.5 3297,1284.46 C24.1@3277.5,1264.96 3300,1242.47 3300,1192 3339,1153 3390.57,1153 3393.39,1155.82 3408.07,1155.82 3420.42,1143.47 U7.11@3420.42,1131.01
NetC24_2: C24.2 R35.2 U7.10 | length 332.4
  Top Layer w10: R35.2@3344,1338.47 3315,1309.47 3315,1290.46 C24.2@3340.5,1264.96 3320,1244.47 3320,1198 3347,1171 3382.01,1171 3384.83,1173.82 3415.53,1173.82 3440.1,1149.24 U7.10@3440.1,1131.01
NetC29_1: C29.1 R41.2 U7.5 | length 234.6
  Top Layer w10: U7.5@3538.53,1131.01 3538.53,1179.44 3560,1200.91 3560,1242.49 C29.1@3542.5,1259.98 3542.5,1262.5 3565,1285 3565,1317.49 R41.2@3549,1333.49
NetC29_2: C29.2 R42.2 U7.4 | length 242.6
  Top Layer w10: U7.4@3558.21,1131.01 3558.21,1173.67 3580,1195.46 3580,1234.49 C29.2@3605.5,1259.98 3605.5,1264.5 3585,1285 3585,1303.2 3614,1332.2 R42.2@3614,1333.49
NetC32_1: C32.1 R45.2 U7.2 | length 305.7
  Top Layer w10: U7.2@3597.58,1131.01 3597.58,1146.57 3639,1187.99 3639,1189 3645,1195 3695,1195 3710,1210 3710,1242.49 C32.1@3692.5,1259.98 3715,1282.48 3715,1307.49 R45.2@3689,1333.49
NetC32_2: C32.2 R48.2 U7.1 | length 304.8
  Top Layer w10: U7.1@3617.27,1131.01 3617.27,1140.8 3653.47,1177 3702.46,1177 3730,1204.54 3730,1234.49 C32.2@3755.5,1259.98 3735,1280.48 3735,1314.49 R48.2@3754,1333.49
NetC34_1: C34.1 R50.2 U7.40 | length 269.3
  Top Layer w10: U7.40@3642.86,947.94 3773.29,947.94 C34.1@3799,973.64 3822.64,950 3860.36,950 R50.2@3882.5,972.15
NetC34_2: C34.2 R51.2 U7.39 | length 264.4
  Top Layer w10: U7.39@3642.86,928.25 3781.4,928.25 C34.2@3799,910.65 3818.35,930 3859.65,930 R51.2@3882.5,907.15
NetC39_1: C39.1 U7.43 Y2.2 | length 1122.7
  Top Layer w10: U7.43@3642.86,1006.99 3705.08,1006.99 3749.09,1051 4334.54,1051 4337,1053.46 4337,1067 4321,1083 4292,1083 4236,1139 Y2.2@4160.99,1139 4030.5,1139 C39.1@3988.5,1097
NetC46_1: C46.1 Q1.3 R53.2 | length 142.9
  Top Layer w15: C46.1@4441.77,830.1 Q1.3@4511,830.1
  Top Layer w20: R53.2@4368.5,831 4369.22,830.28 C46.1@4441.59,830.28 C46.1@4441.77,830.1
NetC47_1: C47.1 Q2.3 R54.2 | length 143.6
  Top Layer w15: R54.2@4368.5,611 4369.99,612.5 C47.1@4442,612.5 4442.18,612.32 Q2.3@4511.41,612.32
NetC48_1: C48.1 U7.42 Y2.1 | length 1161.8
  Top Layer w10: U7.42@3642.86,987.31 3710.85,987.31 3756.54,1033 4342,1033 4362,1053 4362,1066 4377,1081 4405,1081 4463,1139 Y2.1@4535.01,1139 4675,1139 4692.5,1121.5 C48.1@4692.5,1087
NetC55_1: C55.1 D20.3 R52.1 R65.2 U11.2 | length 566.7
  Top Layer w20: R65.2@4770,2654.5 4750,2634.5 4750,2531 4775,2506 C55.1@4775,2501 4755,2481 4755,2356 v1(4765,2346) 4795,2316 U11.2@4795,2277.18
  Bottom Layer w20: D20.3@4681.5,2421 R52.1@4743.5,2421 4765,2399.5 v1(4765,2346)
NetC55_2: C55.2 D19.3 R63.2 U11.3 | length 474.8
  Top Layer w20: U11.3@4695,2277.18 4695,2316 4718,2339 4718,2473 4695,2496 C55.2@4695,2501 4720,2526 4720,2634.5 R63.2@4700,2654.5
  Bottom Layer w20: D19.3@4691.5,2296 4691.5,2322.5 v1(4715,2346)
NetC61_1: C61.1 D18.3 R77.2 R97.1 U12.2 | length 612.5
  Top Layer w20: R77.2@5370,2699.5 5350,2679.5 5350,2566 C61.1@5375,2541 5352,2518 5352,2363 5350,2361 v1(5352,2359) 5380,2331 U12.2@5380,2277.18
  Bottom Layer w20: D18.3@5246.5,2426 5311.5,2426 R97.1@5312.5,2425 5312.5,2406.5 5352,2367 v1(5352,2359)
NetC61_2: C61.2 D17.3 R74.2 U12.3 | length 555.9
  Top Layer w20: U12.3@5280,2277.18 5280,2335.08 5324,2379.08 5324,2512 C61.2@5295,2541 5319.98,2565.98 5319.98,2671 5320,2681 5313.5,2681 R74.2@5295,2699.5
  Bottom Layer w20: D17.3@5249.5,2305 5252,2305 v1(5306,2359)
NetC63_1: C63.1 FB10.1 R76.2 U13.3
NetC68_1: C68.1 D15.3 R89.2 R107.1 U14.2 | length 657.3
  Top Layer w20: R89.2@5957.73,2694.49 5935,2671.75 5935,2573.72 C68.1@5962.73,2545.98 5935,2518.25 5935,2361 v1(5946,2350) 5975,2321 U14.2@5975,2277.18
  Bottom Layer w20: D15.3@5806.5,2425 5902.5,2425 R107.1@5903.5,2424 5903.5,2390.5 5945,2349 v1(5946,2350)
NetC68_2: C68.2 D16.3 R86.2 U14.3 | length 557.7
  Top Layer w20: U14.3@5875,2277.18 5875,2326 v1(5894,2345) 5905,2356 5905,2523.72 C68.2@5882.73,2545.98 5882.73,2553.73 5905,2576 5905,2672.22 R86.2@5882.73,2694.49
  Bottom Layer w20: D16.3@5806.5,2314 5863,2314 v1(5894,2345)
NetC74_2: C74.2 U15.6 | length 93.5
  Bottom Layer w10: U15.6@4113.2,3007.4 4113.2,2914.3 C74.2@4113.5,2914
NetC76_1: C76.1 C79.2 FB13.1 R95.2 U15.1 | length 90.7
  Bottom Layer w15: C76.1@4043.5,3244 4062,3225.5 U15.1@4062,3161
NetC76_2: C76.2 R94.2 R95.1 U15.2 | length 237.8
  Bottom Layer w10: U15.2@4087.6,3161 4087.6,3225.1 C76.2@4106.5,3244 ; R95.1@4106.5,3319 C76.2@4106.5,3244 ; R94.2@4178.5,3244 C76.2@4106.5,3244
NetC86_2: C86.2 FB14.1 U16.3
NetC107_2: C107.2 U19.6 | length 139.1
  Bottom Layer w8: U19.6@3093.2,2905.1 3093.2,2867.5 3103,2857.7 3135,2857.7 3152.3,2875 C107.2@3183.5,2875
NetC111_1: C111.1 R99.2 R100.1 U19.2 | length 290.6
  Bottom Layer w10: U19.2@3067.6,3057 3069,3058.4 3069,3099 3084.5,3114.5 C111.1@3084.5,3143 ; R100.1@3080.5,3211 3084.5,3207 C111.1@3084.5,3143 ; R99.2@3195.5,3102 3154.5,3143 C111.1@3084.5,3143
NetC111_2: C111.2 C115.2 FB17.1 R100.2 U19.1
NetC121_2: C121.2 FB18.1 U20.3
NetC124_2: C124.2 U21.6 | length 139.1
  Bottom Layer w8: U21.6@2060.84,2899.4 2060.84,2861.8 2070.64,2852 2102.64,2852 2119.94,2869.3 C124.2@2151.14,2869.3
NetC127_1: C127.1 R101.2 R102.1 U21.2 | length 242.3
  Bottom Layer w10: U21.2@2037.64,3053 2037.64,3097.1 2066.54,3126 2130.04,3126 R101.2@2155.04,3101 ; C127.1@2066.54,3132.5 R102.1@2066.54,3191
NetC127_2: C127.2 C131.2 FB19.1 R102.2 U21.1
NetC137_2: C137.2 FB20.1 U22.3
NetC140_2: C140.2 U23.6 | length 139.1
  Bottom Layer w8: U23.6@1058.2,2898.4 1058.2,2860.8 1068,2851 1100,2851 1117.3,2868.3 C140.2@1148.5,2868.3
NetC143_1: C143.1 R103.2 R104.1 U23.2 | length 242.3
  Bottom Layer w10: U23.2@1032.6,3052 1032.6,3096.1 C143.1@1061.5,3125 1125,3125 R103.2@1150,3100 ; C143.1@1061.5,3131.5 R104.1@1061.5,3190
NetC143_2: C143.2 C147.2 FB21.1 R104.2 U23.1 | length 302.9
  Bottom Layer w10: C147.2@925,3235 950,3260 FB21.1@998.5,3260 ; C143.2@995,3125 1000,3120 1000,3090 1007,3083 U23.1@1007,3052 ; C143.2@998.5,3126.5 R104.2@998.5,3190 FB21.1@998.5,3260 ; FB21.1@1000,3265 998.5,3263.5 FB21.1@998.5,3260 ; FB21.1@1000.47,3260 FB21.1@998.5,3260
NetC153_2: C153.2 FB22.1 U24.3 | length 228.8
  Bottom Layer w10: FB22.1@525,2990.47 525,2932.09 525,2900 535,2890 610,2890 620,2880 620,2850 U24.3@625,2850
NetD1_2: D1.2 R105.1 | length 239.5
  Top Layer w15: D1.2@267.48,3150 322.48,3205 v1(429,3205)
  Bottom Layer w15: R105.1@428.5,3150 428.5,3204.5 v1(429,3205)
NetD2_1: D2.1 R6.1 | length 226.4
  Top Layer w20: R6.1@1236.5,3355 1236.5,3466.5 1270,3500 D2.1@1270,3567.52
NetD3_2: D3.2 R7.1 | length 279.9
  Top Layer w20: R7.1@1415,3291.5 1415,3570.35 D3.2@1415.75,3571.1
NetD4_1: D4.1 R19.1 | length 252.5
  Top Layer w15: R19.1@2273.63,3355 2320,3355 2365,3400 D4.1@2365,3542.52
NetD5_2: D5.2 R21.1 | length 161
  Top Layer w15: R21.1@2565,3401.5 D5.2@2565,3562.52
NetD6_1: D6.1 R33.1 | length 76
  Top Layer w20: R33.1@3525,3561.5 D6.1@3525,3637.52
NetD9_2: D9.2 R55.1 | length 124.3
  Top Layer w10: R55.1@3760,3541.51 3763,3544.51 D9.2@3763,3664.54
NetD10_1: D10.1 Q2.1 Q2.2 Q2.5 Q2.6 Q2.8 | length 648.6
  Top Layer w15: Q2.6@4562.59,539.68 4804.32,539.68 D10.1@5092,252
NetD10_2: D10.2 R56.1 | length 170.6
  Top Layer w15: R56.1@4922,150.5 5090.5,150.5 D10.2@5092,152
NetD11_1: D11.1 R57.1 | length 81.9
  Top Layer w10: R57.1@4001,3584.5 4001,3663.52 D11.1@4003,3665.52
NetD12_1: D12.1 Q1.1 Q1.2 Q1.5 Q1.6 Q1.8 | length 1194.2
  Top Layer w15: Q1.6@4563.64,756 Q1.6@4562.18,757.46 4642.54,757.46 5030,370 5434,370 D12.1@5547,257
NetD12_2: D12.2 R58.1 | length 175.6
  Top Layer w15: R58.1@5372,155.5 5545.5,155.5 D12.2@5547,157
NetD14_2: D14.2 R76.1 | length 66
  Top Layer w15: R76.1@5618,780.5 D14.2@5618,846.52
NetD21_1: D21.1 D23.2 T5.6
  other v1: 4060,2243 4061,2296
NetD32_1: D32.1 D33.2 T3.6
  other v1: 3040,2260 3050,2305
NetD37_1: D37.1 D39.2 T2.6 | length 60.1
  Top Layer w25: T2.6@1980,2269.84 2039.84,2269.84 2040,2270
  other v1: 2035,2250 2037,2292
NetD43_1: D43.1 D45.2 T1.6 | length 110.1
  Top Layer w25: T1.6@1000,2264.84 T1.6@1000.16,2265
  Top Layer w32: T1.6@1000.16,2265 1060,2265 ; v1@1060,2240 1060,2265 ; 1060,2290 1060,2265
  other v1: 1045,2245 1044,2285
NetFB1_2: FB1.2 R2.1 | length 621
  Top Layer w20: R2.1@610,2733.5 632,2755.5 632,2877 754.68,2999.69 754.68,3263 732.68,3285 FB1.2@732.68,3285.47
NetFB2_1: FB2.1 R1.2 TP2.1 | length 564.5
  Top Layer w20: FB2.1@802.68,3344.53 802.68,3380 782.68,3400 782.68,3532.69 826,3576 R1.2@939.39,3576
  Top Layer w90: R1.2@939.39,3576 TP2.1@939.39,3769.39
  other v2: 1066,3496 1102,3561 1178,3563 1100,3630 1178,3630 1097,3701 1176,3703 1102,3821 1180,3828 1106,3903
NetFB2_2: FB2.2 R4.1 | length 619.4
  Top Layer w20: R4.1@680,2733.5 660,2753.5 660,2865.4 782.68,2988.09 782.68,3265.47 FB2.2@802.68,3285.47
NetFB3_2: FB3.2 R11.1 | length 645.6
  Top Layer w20: R11.1@1671,2721.5 1690,2740.5 1690,2855 1872.32,3037.31 1872.32,3255.47 FB3.2@1852.32,3275.47
NetFB4_1: FB4.1 R9.2 TP5.1 | length 570.7
  Top Layer w20: FB4.1@1922.32,3334.53 1922.32,3370 1902.32,3390 1902.32,3537.31 1935,3570 R9.2@2048.39,3570
  Top Layer w90: R9.2@2048.39,3570 TP5.1@2048.39,3770
  other v2: 2185,3530 2284,3536 2240,3580 2290,3627 2209,3629 2284,3705 2208,3707 2204,3808 2277,3811 2208,3915
NetFB4_2: FB4.2 R14.1 | length 648.1
  Top Layer w20: R14.1@1741,2721.5 1718,2744.5 1718,2843.4 1900.32,3025.72 1900.32,3253.47 FB4.2@1922.32,3275.47
NetFB5_2: FB5.2 R24.1 | length 754.4
  Top Layer w20: R24.1@2679,2707.5 2711,2739.5 2710,2740.5 2710,2895.16 2784.84,2970 2930,2970 3039.71,3079.71 3039.71,3188.45 FB5.2@3012.69,3215.47
NetFB6_1: FB6.1 R22.2 TP8.1 | length 633.1
  Top Layer w20: FB6.1@3092.69,3274.53 3092.69,3311.02 3065.37,3338.34 3065.37,3540.37 3095,3570 R22.2@3208.39,3570
  Top Layer w90: R22.2@3208.39,3570 3208.39,3768.39 TP8.1@3210,3770
  other v2: 3443,3500 3342,3502 3401,3585 3340,3640 3448,3648 3369,3740 3453,3741 3367,3813 3455,3814 3385,3910
NetFB6_2: FB6.2 R26.1 | length 752.4
  Top Layer w20: 2738,2805 2738,2883.56 2794.44,2940 2940,2940 3067.71,3067.71 3067.71,3190.5 FB6.2@3092.69,3215.47 ; 2739,2809 2739,2727.5 R26.1@2759,2707.5
NetFB9_1: FB9.1 J14.1 | length 90.7
  Bottom Layer w30: J14.1@4713.72,3782 4795.91,3782 FB9.1@4801.91,3788
NetFB9_2: FB9.2 R67.1 | length 100.5
  Bottom Layer w30: R67.1@4905,3692.09 4916.09,3703.17 FB9.2@4916.09,3788
NetFB11_1: FB11.1 J15.1 | length 93.9
  Top Layer w30: J15.1@5322.72,3774 J15.1@5323.64,3773.09
  Bottom Layer w30: J15.1@5322.72,3774 5323.72,3773 FB11.1@5414.91,3773
NetFB11_2: FB11.2 R79.1 | length 119.1
  Bottom Layer w30: R79.1@5502,3665.09 5529.09,3692.17 FB11.2@5529.09,3773
NetFB12_1: FB12.1 J16.1 | length 86.2
  Bottom Layer w30: J16.1@5909.72,3774 FB12.1@5995.91,3774
NetFB12_2: FB12.2 R90.1 | length 124.6
  Bottom Layer w30: R90.1@6077,3663.09 6110.09,3696.17 FB12.2@6110.09,3774
NetJ3_12: J3.12 R8.1 | length 576.9
  Top Layer w10: R8.1@2204,425 2234,395 2234,248 2375,107 2498,107 J3.12@2544,153
NetJ3_14: J3.14 R10.1 | length 415.1
  Top Layer w10: R10.1@2274,427 2252,405 2252,255.46 2354.46,153 J3.14@2444,153
NetR3_1: R3.1 U1.6 | length 210.9
  Top Layer w10: U1.6@600,1938.82 600,1910 642,1868 642,1783.5 R3.1@615,1756.5
NetR5_1: R5.1 U1.7 | length 211.3
  Top Layer w10: R5.1@690,1756.5 660,1786.5 660,1870 700,1910 U1.7@700,1938.82
NetR12_1: R12.1 U3.6 | length 196.3
  Top Layer w10: U3.6@1660,1938.82 1660,1905 1700,1865 1700,1801.5 R12.1@1670,1771.5
NetR15_1: R15.1 U3.7 | length 196.3
  Top Layer w10: R15.1@1750,1771.5 1750,1772.78 1720,1802.78 1720,1860 1760,1900 U3.7@1760,1938.82
NetR23_1: R23.1 U5.6 | length 187.6
  Top Layer w10: U5.6@2663.98,1938.82 2663.98,1901.02 2700,1865 2700,1801.5 R23.1@2675,1776.5
NetR25_1: R25.1 U5.7 | length 190.9
  Top Layer w10: R25.1@2745,1776.5 2745,1784.98 2720,1809.98 2720,1860 2763.98,1903.98 U5.7@2763.98,1938.82
NetR60_2: R60.2 R61.2 R65.1 R70.2 | length 593.1
  Top Layer w20: v1(4631,3190) 4767.81,3053.19 R60.2@4767.81,2973 R61.2@4767.81,2828 4765.72,2825.91 4770,2821.64 R65.1@4770,2717.5
  Bottom Layer w20: v1(4631,3190) 4690.91,3190 R70.2@4691.91,3191
NetR64_1: R64.1 U11.6 | length 198.4
  Top Layer w10: U11.6@4695,1924.82 4695,1896 4745,1846 4745,1782.5 R64.1@4720,1757.5
NetR66_1: R66.1 U11.7 | length 188
  Top Layer w10: R66.1@4785,1757.5 4765,1777.5 4765,1798.37 4765,1840.12 4765,1861 4795,1891 U11.7@4795,1924.82
NetR67_2: R67.2 R68.1 | length 83.2
  Bottom Layer w30: R68.1@4904,3495.09 4905,3496.09 R67.2@4905,3577.91
NetR68_2: R68.2 R69.1 | length 80.5
  Bottom Layer w30: R68.2@4904,3380.91 4904,3306.09 R69.1@4908,3302.09
NetR69_2: R69.2 R70.1 | length 102.5
  Bottom Layer w20: R70.1@4806.09,3191 4892.91,3191 R69.2@4904,3179.91
NetR72_2: R72.2 R73.2 R77.1 R82.2 | length 544.6
  Top Layer w20: v1(5224,3169) 5247,3169 5365.81,3050.19 R72.2@5365.81,3024 R73.2@5365.81,2879 5365.81,2766.69 R77.1@5370,2762.5
  Bottom Layer w20: v1(5224,3169) 5227,3172 R82.2@5286.91,3172
NetR75_1: R75.1 U12.6 | length 176.3
  Top Layer w10: U12.6@5280,1924.82 5280,1891 5325,1846 5325,1802.5 R75.1@5300,1777.5
NetR78_1: R78.1 U12.7 | length 172.2
  Top Layer w10: R78.1@5370,1777.5 5345,1802.5 5345,1856 5380,1891 U12.7@5380,1924.82
NetR79_2: R79.2 R80.1 | length 87.2
  Bottom Layer w30: R80.1@5501,3464.09 5502,3465.09 R79.2@5502,3550.91
NetR80_2: R80.2 R81.1 | length 86.2
  Bottom Layer w30: R80.2@5501,3349.91 5501,3265.09 R81.1@5502,3264.09
NetR81_2: R81.2 R82.1 | length 113.9
  Bottom Layer w20: R82.1@5398.09,3174 5422.17,3149.91 R81.2@5502,3149.91
NetR84_2: R84.2 R85.2 R89.1 R93.2 | length 568
  Top Layer w20: v1(5816,3160) 5860.09,3160 R85.2@5980.09,3040 R84.2@5980.09,2913 5980.09,2779.83 R89.1@5957.73,2757.48
  Bottom Layer w20: v1(5816,3160) 5822,3166 R93.2@5875.91,3166
NetR87_1: R87.1 U14.6 | length 174.2
  Top Layer w10: U14.6@5875,1924.82 5875,1886 5915,1846 5915,1802.5 R87.1@5890,1777.5
NetR88_1: R88.1 U14.7 | length 172.2
  Top Layer w10: R88.1@5955,1777.5 5935,1797.5 5935,1851 5975,1891 U14.7@5975,1924.82
NetR90_2: R90.2 R91.1 | length 87.7
  Bottom Layer w30: R90.2@6077,3548.91 6077,3464.09 R91.1@6079,3462.09
NetR91_2: R91.2 R92.1 | length 85.5
  Bottom Layer w20: R91.2@6079,3347.91 6083,3343.91 R92.1@6083,3264.09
